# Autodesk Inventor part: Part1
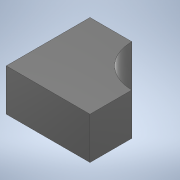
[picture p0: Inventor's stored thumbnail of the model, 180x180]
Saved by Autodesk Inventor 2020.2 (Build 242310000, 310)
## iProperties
Created: 2020-01
Part Number: Part1
Material: UHMW, Black
Document SubType Name: Modeling
Designer: thira
Density: 0.94 g/cm^3
Appearance: Smooth - Black
Author: thira
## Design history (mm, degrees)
sketch "Sketch1"
  geometry: L1 (0, 0)-(0, -20); L2 (0, -20)-(-10, -20); L3 (-20, -10)-(-20, 0); L4 (0, 0)-(-20, 0); A1 r 10 centre (-20, -20) between (-10, -20) and (-20, -10)
  constraints: 8 end point, 2 horizontal, 2 perpendicular, 2 point on circle, 1 centre point, 1 point on line, 1 vertical
  dimensions: "d0" = 20 distance of L1.start L1.end; "d1" = 10 distance of L1.end L2.end; "d3" = 20 distance of L1.start L3.end
extrude "Extrusion1" new body sketch "Sketch1" distance "d4" = 10; taper "d5" = 0 deg
body "Solid1"
